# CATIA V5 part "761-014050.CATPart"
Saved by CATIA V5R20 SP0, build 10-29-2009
Part number: 761-014050
Source: Unknown
Property "ARTICLENO": "761-014050"
Property "BOMINFO": "761-014050"
Property "CODE": "761-014050"
Property "H": "14.000"
Property "L1": "50.000"
Property "L2": "32.000"
Property "LINA": "761-014050"
Property "NB": "761-014050"
Property "NBSYN": "$CODE."
Property "NN": "761"
Property "NT": "VW/AUDI Keys"
Property "P": "0.000"
Property "SUPPLIER": "CF"
Bounding box of the stored display mesh (mm): x -25 to 25, y 0 to 14, z -11 to 11
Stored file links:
  C:\Users\Utente\Desktop\3D files 761\761-014050.CATPart
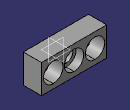
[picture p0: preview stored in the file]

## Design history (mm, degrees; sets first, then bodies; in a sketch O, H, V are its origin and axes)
Body1 "Geometry.1" (main body)
  Solid1 "761-014050.catpart": solid without history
